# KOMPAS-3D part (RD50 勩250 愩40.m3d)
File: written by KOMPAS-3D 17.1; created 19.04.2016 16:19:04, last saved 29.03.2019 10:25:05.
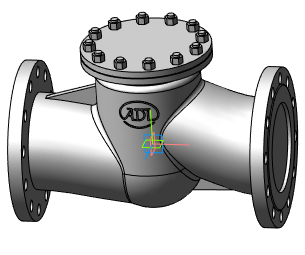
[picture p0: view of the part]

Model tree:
1. Операция без истории:2  (labels: Сталь 20  ГОСТ 1050-88)

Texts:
  RD50 Ду15 Ру40
  RD50 Ду20 Ру40
  RD50 Ду25 Ру40
  RD50 Ду32 Ру40
  RD50 Ду40 Ру40
  RD50 Ду50 Ру40
  RD50 Ду65 Ру40
  RD50 Ду80 Ру40
  RD50 Ду100 Ру40
  RD50 Ду125 Ру40
  RD50 Ду150 Ру40
  RD50 Ду200 Ру40
  RD50 Ду250 Ру40
  RD50 Ду300 Ру40
  RD50 Ду350 Ру40
  RD50 Ду400 Ру40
